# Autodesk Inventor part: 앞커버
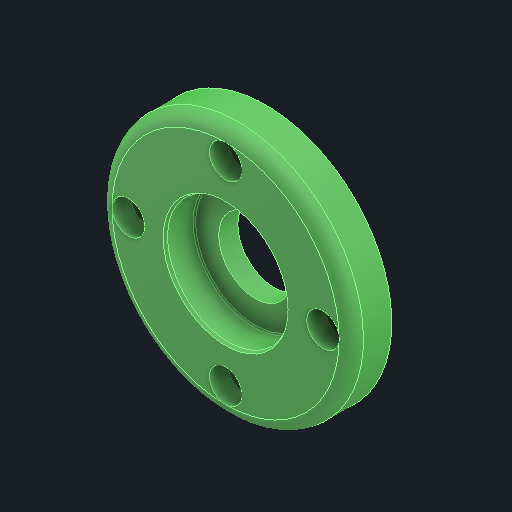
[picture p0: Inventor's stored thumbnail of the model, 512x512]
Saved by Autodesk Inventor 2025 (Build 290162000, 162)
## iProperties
Created: 2025-08
Part Number: 앞커버
Material: 알루미늄 6061
Document SubType Name: Modeling
Designer: infra006
Density: 2.71 g/cm^3
Appearance: 기본값
Author: jhkim
Sending System: Autodesk Inventor 2026
Preprocessor: ST-DEVELOPER v20.1
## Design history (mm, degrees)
feature "솔리드1"
node "솔리드2"
